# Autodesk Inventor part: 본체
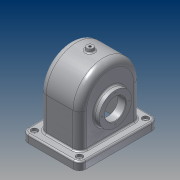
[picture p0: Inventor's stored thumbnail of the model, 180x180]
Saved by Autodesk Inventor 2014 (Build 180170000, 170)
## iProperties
Created: 2016-10
Part Number: 본체
Material: 알루미늄 6061
Document SubType Name: Modeling
Designer: USER
Density: 2.71 g/cm^3
Appearance: 알루미늄 - 평지
Author: USER
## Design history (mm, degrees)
sketch "스케치1"
  geometry: L1 (-55, -75)-(55, -75); L2 (55, -75)-(55, 75); L3 (55, 75)-(-55, 75); L4 (-55, 75)-(-55, -75); L5 (-55, -75)-(55, 75); L6 (55, -75)-(-55, 75); 3 further points
  constraints: 12 end point, 3 midpoint, 2 parallel, 1 coincident, 1 horizontal, 1 perpendicular
  dimensions: "d0" = 110 distance of L2.end L3.end; "d1" = 150 distance of L1.end L2.end
extrude "돌출1" new body sketch "스케치1" distance "d2" = 15; taper "d3" = 0 deg
fillet "모깎기1" dims "d4" = 12
sketch "스케치2"
  geometry: L1 (-58, 0)-(-58, 80); L2 (58, 80)-(58, 0); L3 (58, 0)-(-58, 0); A1 r 58 centre (0, 80) between (58, 80) and (-58, 80); 1 further point
  constraints: 6 end point, 2 point on circle, 2 tangent, 1 centre point, 1 midpoint, 1 parallel, 1 perpendicular, 1 vertical, 1 vertical alignment
  dimensions: "d5" = 80 distance from line of L3 A1.centre; "d6" = 58 radius of A1
extrude "돌출2" join sketch "스케치2" stored distance "d7" = 77; taper "d8" = 0 deg
fillet "모깎기2" dims "d9" = 13
sketch "스케치3"
  geometry: L1 (0, -63)-(0, 63) reference; C1 r 31 at (-65, 0); 2 further points
  constraints: 1 centre point, 1 horizontal alignment, 1 midpoint
  dimensions: "d10" = 62 diameter of C1; "d11" = 65 distance from line of L1 C1.centre
extrude "돌출3" join sketch "스케치3" distance "d12" = 10; taper "d13" = 0 deg
fillet "모깎기3" dims "d14" = 3
fillet "모깎기4" dims "d15" = 3
sketch "스케치4"
  geometry: L1 (63, 0)-(-63, 0) reference; L2 (-52, 0)-(-52, 80); L3 (52, 80)-(52, 0); A1 r 52 centre (0, 80) between (52, 80) and (-52, 80); A2 r 58 centre (0, 80) between (58, 80) and (-58, 80) reference; 1 further point
  constraints: 4 end point, 2 point on circle, 2 point on line, 2 tangent, 1 centre point, 1 concentric, 1 parallel, 1 perpendicular
  dimensions: "d16" = 52 radius of A1
extrude "돌출4" cut sketch "스케치4" stored distance "d17" = 67; taper "d18" = 0 deg
fillet "모깎기5" dims "d19" = 8
sketch "스케치5"
  geometry: L1 (33.5, 65)-(19.5, 65); L2 (19.5, 65)-(19.5, 93); L3 (19.5, 93)-(33.5, 104.747); L4 (33.5, 104.747)-(33.5, 65); L5 (-25.5, 0)-(25.5, 0) reference; L6 (33.5, 80)-(33.5, 0) reference; 1 further point
  constraints: 8 end point, 1 collinear, 1 horizontal, 1 parallel, 1 perpendicular
  dimensions: "d20" = 65 distance between parallel lines of L1 L5; "d21" = 50 deg angle of L2 L3; "d22" = 56 diameter of L2.end L1; "d23" = 14 distance of L1.start L1.end
revolve "회전1" sketch "스케치5" stored, may be unused: angle "d24" = 90 deg
fillet "모깎기6" dims "d25" = 3
sketch "스케치6"
  geometry: L1 (0, 63)-(0, -63) reference; C1 r 37.5 at (65, 0); 1 further point
  constraints: 1 centre point, 1 horizontal alignment
  dimensions: "d26" = 75 diameter of C1; "d27" = 65 distance from line of L1 C1.centre
extrude "돌출5" join sketch "스케치6" distance "d28" = 5; taper "d29" = 0 deg
fillet "모깎기7" dims "d30" = 3
hole "구멍1" diameter "d33" = 40; stored, may be unused: countersink angle "d37" = 90 deg, drill point angle "d39" = 118 deg; dims "d31" = 10, "d32" = 10, "d34" = 6, "d35" = 4, "d36" = 2, "d38" = 8
chamfer "모따기1" distance "d40" = 1; stored, may be unused: second distance "d41" = 2, angle "d42" = 45 deg
node "작업 평면1"
sketch "스케치7"
  geometry: C1 r 6 at (0, 0); 1 further point
  constraints: 1 centre point, 1 coincident
  dimensions: "d44" = 12 diameter of C1
extrude "돌출6" join sketch "스케치7" distance "d45" = 10; taper "d46" = 10 deg
fillet "모깎기8" dims "d47" = 3
hole "구멍2" diameter "d50" = 4.459; stored, may be unused: countersink angle "d54" = 90 deg, drill point angle "d56" = 118 deg; dims "d48" = 10, "d49" = 10, "d51" = 20, "d52" = 4, "d53" = 2, "d55" = 8
sketch "스케치8"
  geometry: C1 r 31 at (0, 0) reference; 2 further points
  constraints: 1 horizontal alignment
  dimensions: "d57" = 26 distance of C1.centre point (-26, 0)
hole "구멍3" sketch "스케치8" at (-26, 0) diameter "d58" = 2.459; stored, may be unused: countersink angle "d62" = 90 deg, drill point angle "d64" = 118 deg; dims "d59" = 6, "d60" = 4, "d61" = 2, "d63" = 8
sketch "스케치9"
  geometry: C1 r 37.5 at (0, 0) reference; 2 further points
  constraints: 1 horizontal alignment
  dimensions: "d68" = 29 distance of point (29, 0) C1.centre
hole "구멍4" sketch "스케치9" at (29, 0) diameter "d69" = 2.459; stored, may be unused: countersink angle "d73" = 90 deg, drill point angle "d75" = 118 deg; dims "d70" = 6, "d71" = 4, "d72" = 2, "d74" = 8
fillet "모깎기9" dims "d79" = 3
hole "구멍5" diameter "d82" = 5; stored, may be unused: countersink angle "d86" = 90 deg, drill point angle "d88" = 118 deg; dims "d80" = 10, "d81" = 10, "d83" = 6, "d84" = 12, "d85" = 5, "d87" = 8
node "솔리드1"
pattern_circular "원형 패턴1" dims angle "d66" = 360 deg
pattern_circular "원형 패턴2" dims angle "d77" = 360 deg
mirror "대칭1"
mirror "대칭2"
other parameters: "d43" = 144
